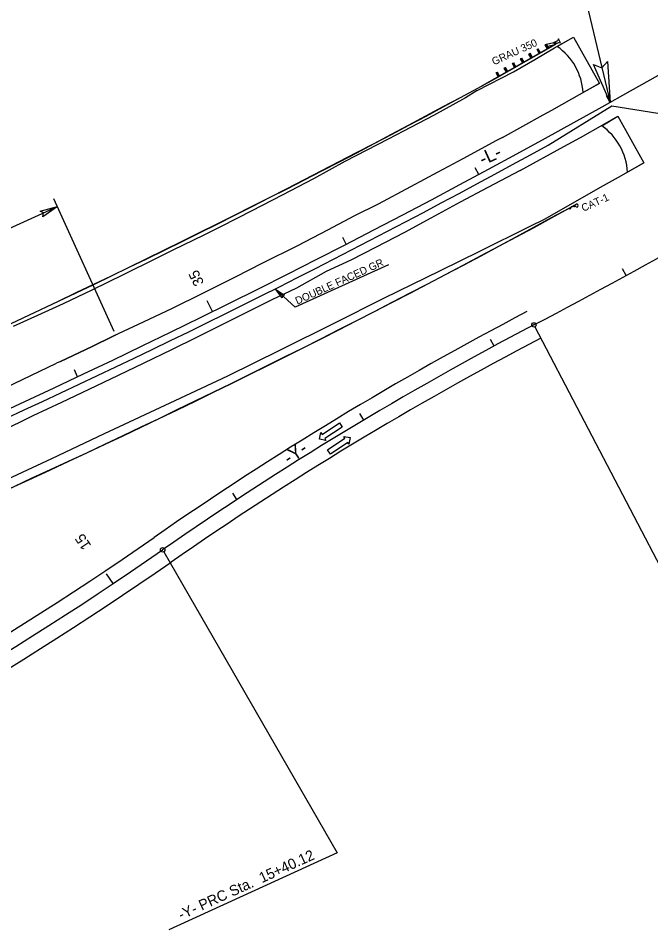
# Model space of a CAD drawing. Extents: x 2242984 to 2250974, y 661492 to 664681.
# Drawn here: x 2249828 to 2250250, y 663412 to 664020 of the extents above; entities that cross this region are included whole.
import ezdxf

# ---------------------------------------------------------------- set-up
doc = ezdxf.new("R2010")
doc.units = 0
for name, color, linetype in [('Prop Dimension', 7, 'Continuous'), ('Prop DSN Text', 7, 'Continuous'), ('Prop EOT Dash', 7, 'Continuous'), ('Prop Guardrail', 7, 'Continuous'), ('Prop Guardrail Anchor Unit CELL', 7, 'Continuous'), ('Prop Guardrail Double Faced', 7, 'Continuous'), ('Prop Horizontal Alignment', 7, 'Continuous'), ('Prop Horizontal Alignment Curve and Spiral Data', 7, 'Continuous'), ('Prop Horizontal Alignment Station Label', 7, 'Continuous'), ('Prop Horizontal Alignment Tick Label', 7, 'Continuous'), ('Prop Horizontal Alignment Tick Large', 7, 'Continuous'), ('Prop Horizontal Alignment Tick Small', 7, 'Continuous'), ('Prop Lane Arrow CELL', 7, 'Continuous'), ('Prop Paved Shoulder', 7, 'Continuous'), ('Prop Shade Medium', 7, 'Continuous'), ('Prop Terminator CELL', 7, 'Continuous'), ('Scratch_Level_2', 7, 'Continuous'), ('Scratch_Level_6', 7, 'Continuous'), ('Typical Terminator CELL', 7, 'Continuous')]:
    doc.layers.add(name, color=color, linetype=linetype)

# ---------------------------------------------------------------- blocks, each defined once
blk = doc.blocks.new('TERMINATOR')
at = {"layer": 'Typical Terminator CELL'}
blk.add_lwpolyline([(-0.469, 0.081), (0, 0), (-0.471, -0.083), (-0.411, 0)], close=True, dxfattribs=at)

msp = doc.modelspace()

# ---------------------------------------------------------------- linework, layer by layer
at = {"layer": 'Prop Dimension'}
for p, q in [((2250142.17, 664305.26), (2250223.29, 663964)), ((2250224.53, 663961.77), (2250255.11, 663956.78)), ((2249892.16, 663811.07), (2249851.91, 663899.68)), ((2249394.77, 663685.73), (2249854.28, 663894.46))]:
    msp.add_line(p, q, dxfattribs=at)
at = {"layer": 'Prop DSN Text'}
for p in [(2250075.36, 663855.62), (2250000.07, 663839)]:
    msp.add_line(p, (2250013.07, 663827.24), dxfattribs=at)
at = {"layer": 'Prop EOT Dash'}
for centre, radius, start, end in [((2251237.28, 661776.78), 2310, 117.57881, 124.80379), ((2251237.28, 661776.78), 2290, 117.57881, 124.80379), ((2248611.75, 665553.89), 2290, 294.41783, 304.80379), ((2248611.75, 665553.89), 2310, 294.41783, 304.80379)]:
    msp.add_arc(centre, radius, start, end, dxfattribs=at)
at = {"layer": 'Prop Guardrail'}
for radius, start, end in [(5678.58, 294.43013, 298.65426), (5778.08, 294.430126, 298.67506)]:
    msp.add_arc((2247423.42, 668962.88), radius, start, end, dxfattribs=at)
at = {"layer": 'Prop Guardrail Anchor Unit CELL'}
for p, q in [((2250146.43, 663979.76), (2250187.02, 664002.95)), ((2250179.95, 664002.43), (2250180.82, 664002.93)), ((2250181.47, 663999.77), (2250179.95, 664002.43)), ((2250181.57, 664001.6), (2250179.95, 664002.43)), ((2250180.82, 664002.93), (2250180.71, 664001.1)), ((2250180.82, 664002.93), (2250185.85, 664004)), ((2250182.33, 664000.27), (2250180.82, 664002.93)), ((2250181.57, 664001.6), (2250186.59, 664002.7)), ((2250185.85, 664004), (2250186.71, 664004.5)), ((2250185.85, 664004), (2250186.28, 664004.25)), ((2250186.59, 664002.7), (2250185.85, 664004)), ((2250187.46, 664003.2), (2250185.85, 664004)), ((2250188.22, 664005.08), (2250186.43, 664004.1)), ((2250186.43, 664004.1), (2250186.72, 664003.57)), ((2250186.71, 664004.5), (2250186.59, 664002.7)), ((2250187.46, 664003.2), (2250186.71, 664004.5)), ((2250186.72, 664003.57), (2250187.02, 664003.03)), ((2250187.02, 664003.03), (2250188.81, 664004.01)), ((2250188.84, 664006.4), (2250188.22, 664005.08)), ((2250188.81, 664004.01), (2250190.26, 664003.82)), ((2250190.26, 664003.82), (2250188.84, 664006.4)), ((2250168.97, 663996.25), (2250169.83, 663996.74)), ((2250170.52, 663993.52), (2250168.97, 663996.25)), ((2250170.61, 663995.38), (2250168.97, 663996.25)), ((2250169.83, 663996.74), (2250169.74, 663994.88)), ((2250171.39, 663994.02), (2250169.83, 663996.74)), ((2250174.51, 663999.25), (2250175.37, 663999.75)), ((2250175.99, 663996.65), (2250174.51, 663999.25)), ((2250176.12, 663998.45), (2250174.51, 663999.25)), ((2250175.37, 663999.75), (2250175.25, 663997.95)), ((2250175.25, 663997.95), (2250176.12, 663998.45)), ((2250175.25, 663997.95), (2250176.86, 663997.14)), ((2250176.86, 663997.14), (2250175.37, 663999.75)), ((2250175.99, 663996.65), (2250176.12, 663998.45)), ((2250180.71, 664001.1), (2250181.57, 664001.6)), ((2250180.71, 664001.1), (2250182.33, 664000.27)), ((2250181.47, 663999.77), (2250181.57, 664001.6)), ((2250158.07, 663989.92), (2250158.94, 663990.42)), ((2250159.58, 663987.27), (2250158.07, 663989.92)), ((2250159.69, 663989.09), (2250158.07, 663989.92)), ((2250158.94, 663990.42), (2250158.82, 663988.6)), ((2250160.45, 663987.77), (2250158.94, 663990.42)), ((2250163.54, 663993.03), (2250164.41, 663993.53)), ((2250165.05, 663990.4), (2250163.54, 663993.03)), ((2250165.17, 663992.21), (2250163.54, 663993.03)), ((2250164.41, 663993.53), (2250164.3, 663991.72)), ((2250164.3, 663991.72), (2250165.17, 663992.21)), ((2250164.3, 663991.72), (2250165.92, 663990.89)), ((2250165.92, 663990.89), (2250164.41, 663993.53)), ((2250165.05, 663990.4), (2250165.17, 663992.21)), ((2250165.05, 663990.4), (2250165.92, 663990.89)), ((2250169.74, 663994.88), (2250170.61, 663995.38)), ((2250169.74, 663994.88), (2250171.39, 663994.02)), ((2250170.52, 663993.52), (2250170.61, 663995.38)), ((2250147.15, 663983.63), (2250148.02, 663984.12)), ((2250148.02, 663984.12), (2250147.89, 663982.33)), ((2250149.5, 663981.52), (2250148.02, 663984.12)), ((2250152.59, 663986.8), (2250153.46, 663987.29)), ((2250154.11, 663984.15), (2250152.59, 663986.8)), ((2250154.22, 663985.97), (2250152.59, 663986.8)), ((2250153.46, 663987.29), (2250153.35, 663985.47)), ((2250153.35, 663985.47), (2250154.22, 663985.97)), ((2250153.35, 663985.47), (2250154.98, 663984.64)), ((2250154.98, 663984.64), (2250153.46, 663987.29)), ((2250154.11, 663984.15), (2250154.22, 663985.97)), ((2250158.82, 663988.6), (2250159.69, 663989.09)), ((2250158.82, 663988.6), (2250160.45, 663987.77)), ((2250159.58, 663987.27), (2250159.69, 663989.09)), ((2250148.64, 663981.02), (2250147.15, 663983.63)), ((2250148.76, 663982.82), (2250147.15, 663983.63)), ((2250147.89, 663982.33), (2250148.76, 663982.82)), ((2250147.89, 663982.33), (2250149.5, 663981.52)), ((2250148.76, 663982.82), (2250148.64, 663981.02)), ((2250148.64, 663981.02), (2250149.5, 663981.52)), ((2250149.5, 663981.52), (2250148.76, 663982.82)), ((2250195.98, 663893.45), (2250199.09, 663895.15)), ((2250195.98, 663893.45), (2250196.6, 663893.79)), ((2250196.37, 663892.74), (2250195.98, 663893.45)), ((2250195.98, 663893.45), (2250196.98, 663893.08)), ((2250196.6, 663893.79), (2250196.37, 663892.74)), ((2250196.98, 663893.08), (2250196.37, 663892.74)), ((2250196.6, 663893.79), (2250196.98, 663893.08)), ((2250199.21, 663894.75), (2250197.35, 663894.2)), ((2250198.71, 663894.94), (2250199.33, 663895.27)), ((2250199.1, 663894.23), (2250198.71, 663894.94)), ((2250198.71, 663894.94), (2250199.71, 663894.57)), ((2250199.09, 663895.15), (2250200.6, 663895.97)), ((2250199.21, 663895.21), (2250199.09, 663895.15)), ((2250199.33, 663895.27), (2250199.1, 663894.23)), ((2250199.71, 663894.57), (2250199.1, 663894.23)), ((2250199.33, 663895.27), (2250199.71, 663894.57)), ((2250200.66, 663894.2), (2250199.66, 663894.65))]:
    msp.add_line(p, q, dxfattribs=at)
msp.add_ellipse((2250201.08, 663895.1), major_axis=(-0.475, 0.872), ratio=0.995379, start_param=2.210226, end_param=6.283185, dxfattribs=at)
at = {"layer": 'Prop Guardrail Double Faced'}
msp.add_line((2250181.96, 663935.37), (2250224.53, 663961.77), dxfattribs=at)
msp.add_arc((2247423.42, 668962.88), 5734.58, 294.430126, 298.75316, dxfattribs=at)
at = {"layer": 'Prop Horizontal Alignment'}
for centre, radius, start, end in [((2247423.42, 668962.88), 5729.58, 294.43013, 308.28013), ((2248552.07, 666917.75), 3500, 297.57881, 302.00527), ((2251237.28, 661776.78), 2300, 117.57881, 124.80379), ((2248611.75, 665553.89), 2300, 294.41783, 304.80379)]:
    msp.add_arc(centre, radius, start, end, dxfattribs=at)
at = {"layer": 'Prop Horizontal Alignment Station Label'}
for p, q in [((2250173.15, 663814.11), (2250278.27, 663612.84)), ((2249925.26, 663664.03), (2250041.16, 663462.96)), ((2250041.16, 663462.96), (2249928.6, 663411.67))]:
    msp.add_line(p, q, dxfattribs=at)
for centre in [(2250172.45, 663815.44), (2250172.45, 663815.44), (2249924.52, 663665.33), (2249924.52, 663665.33)]:
    msp.add_circle(centre, 1.5, dxfattribs=at)
at = {"layer": 'Prop Horizontal Alignment Tick Large'}
for p, q in [((2249957.83, 663824.32), (2249954.29, 663831.49)), ((2249891.38, 663642.72), (2249886.93, 663649.37))]:
    msp.add_line(p, q, dxfattribs=at)
at = {"layer": 'Prop Horizontal Alignment Tick Small'}
for p, q in [((2250223.29, 663964), (2250220.84, 663968.36)), ((2250135.62, 663915.9), (2250133.25, 663920.3)), ((2250047.12, 663869.33), (2250044.83, 663873.78)), ((2250234.04, 663848.39), (2250231.64, 663852.78)), ((2250145.83, 663801.31), (2250143.45, 663805.71)), ((2249867.76, 663780.87), (2249865.63, 663785.39)), ((2250058.86, 663751.95), (2250056.3, 663756.25)), ((2249974.12, 663698.87), (2249971.38, 663703.05))]:
    msp.add_line(p, q, dxfattribs=at)
at = {"layer": 'Prop Lane Arrow CELL'}
for p, q in [((2250030.95, 663742.35), (2250042.65, 663750.03)), ((2250044.46, 663747.27), (2250032.76, 663739.59)), ((2250042.65, 663750.03), (2250044.46, 663747.27)), ((2250029.25, 663739.2), (2250030.12, 663743.6)), ((2250030.12, 663743.6), (2250030.95, 663742.35)), ((2250046.29, 663739.77), (2250045.45, 663741.02)), ((2250045.45, 663741.02), (2250049.8, 663740.2)), ((2250033.58, 663738.33), (2250029.25, 663739.2)), ((2250032.76, 663739.59), (2250033.58, 663738.33)), ((2250034.66, 663731.97), (2250046.29, 663739.77)), ((2250048.13, 663737.03), (2250036.5, 663729.23)), ((2250048.96, 663735.79), (2250048.13, 663737.03)), ((2250049.8, 663740.2), (2250048.96, 663735.79)), ((2250036.5, 663729.23), (2250034.66, 663731.97))]:
    msp.add_line(p, q, dxfattribs=at)
at = {"layer": 'Prop Paved Shoulder'}
for p, q in [((2249877.49, 663801.04), (2249891.38, 663807.97)), ((2249891.38, 663807.97), (2249893.19, 663808.8)), ((2249856.27, 663791.12), (2249877.49, 663801.04)), ((2249437.63, 663591.42), (2249853.74, 663789.97))]:
    msp.add_line(p, q, dxfattribs=at)
for points in [[(2250158.72, 663984.49), (2250173.08, 663992.65), (2250186.18, 664000.31), (2250198.89, 664007.57)], [(2250134.59, 663971.94), (2250158.72, 663984.49)], [(2250134.59, 663971.94), (2250126.82, 663967.1), (2250105.33, 663955.19), (2250085.39, 663944.79), (2250075.11, 663939.48), (2250046.26, 663924.42), (2250025.26, 663912.92), (2250004.43, 663901.99), (2249983.97, 663891.5), (2249963.67, 663881.2), (2249951.96, 663875.41), (2249931.42, 663865.38), (2249920.19, 663859.82), (2249898.1, 663848.94), (2249877.27, 663838.63), (2249858.19, 663829.56), (2249843.45, 663822.95), (2249824.73, 663814.35)], [(2250178.7, 663955.71), (2250184.3, 663958.78), (2250216.15, 663976.74)], [(2250151.36, 663940.62), (2250178.7, 663955.71)], [(2250192.4, 663934.62), (2250203.58, 663940.63), (2250218.57, 663948.92), (2250228.5, 663954.7)], [(2250151.36, 663940.62), (2250147.39, 663938.44), (2250124.88, 663926.39), (2250108.36, 663917.42), (2250090.02, 663907.52), (2250068.46, 663896.14), (2250052.71, 663888.16), (2250034.57, 663878.68), (2250014.61, 663868.32), (2249991.28, 663856.62), (2249972.95, 663847.39), (2249951.67, 663836.73), (2249930.54, 663826.11), (2249908.26, 663815.71), (2249891.38, 663807.97), (2249877.49, 663801.04), (2249856.27, 663791.12), (2249853.74, 663789.97)], [(2250163.18, 663918.53), (2250192.4, 663934.62)], [(2250216.95, 663907.43), (2250229.03, 663914.01), (2250245.85, 663923.72)], [(2250163.18, 663918.53), (2250141.76, 663907.17), (2250123.19, 663897.33), (2250103.59, 663886.75), (2250085.93, 663877.2), (2250066.71, 663867.19), (2250050.24, 663858.7), (2250033.81, 663851.08), (2250013.9, 663840.08), (2249997.54, 663832.27), (2249982.72, 663824.86), (2249962.36, 663814.71), (2249947.05, 663807.05), (2249930.38, 663798.85), (2249911.87, 663789.95), (2249894.79, 663781.72), (2249875.22, 663772.32), (2249857.01, 663763.64), (2249837.93, 663754.68), (2249815.49, 663743.88), (2249803.29, 663738.06), (2249784.26, 663729.26), (2249767.73, 663721.96), (2249763, 663719.65)], [(2250179.91, 663886.23), (2250216.95, 663907.43)], [(2249763.05, 663685.31), (2249811.06, 663707.92), (2249850.56, 663726.37), (2249885.63, 663742.92), (2249932.97, 663765.08), (2249967.97, 663781.54), (2250003.28, 663798.87), (2250039.45, 663816.82), (2250072.29, 663833.2), (2250110.04, 663851.84), (2250136.3, 663864.69), (2250169.45, 663881.11), (2250179.91, 663886.23)]]:
    msp.add_lwpolyline(points, dxfattribs=at)
at = {"layer": 'Prop Shade Medium'}
for p, q in [((2250188.01, 664001.35), (2250198.89, 664007.57)), ((2250198.89, 664007.57), (2250216.24, 663976.59)), ((2250216.24, 663976.59), (2250205.25, 663970.59)), ((2250217.69, 663948.44), (2250228.5, 663954.7)), ((2250228.5, 663954.7), (2250245.85, 663923.72)), ((2250245.85, 663923.72), (2250234.94, 663917.42))]:
    msp.add_line(p, q, dxfattribs=at)
for centre, radius, start, end in [((2250164.87, 663968.16), 40.46, 3.44001, 55.1119), ((2250194.29, 663915.12), 40.72, 3.24076, 54.91264)]:
    msp.add_arc(centre, radius, start, end, dxfattribs=at)
at = {"layer": 'Prop Terminator CELL'}
for points in [[(2250221.57, 663991.34), (2250223.29, 663964), (2250212.34, 663989.3), (2250217.81, 663987.06)], [(2250004.3, 663833.61), (2250000.07, 663839), (2250005.91, 663835.34), (2250004.47, 663835.02)]]:
    msp.add_lwpolyline(points, close=True, dxfattribs=at)
at = {"layer": 'Scratch_Level_2'}
for points in [[(2250158.72, 663984.49), (2250173.08, 663992.65), (2250186.18, 664000.31), (2250198.89, 664007.57)], [(2250134.59, 663971.94), (2250158.72, 663984.49)], [(2250216.95, 663907.43), (2250229.03, 663914.01), (2250245.85, 663923.72)], [(2250179.91, 663886.23), (2250216.95, 663907.43)]]:
    msp.add_lwpolyline(points, dxfattribs=at)
at = {"layer": 'Scratch_Level_6'}
for p, q in [((2250146.38, 663979.85), (2250186.97, 664003.03)), ((2250196.03, 663893.37), (2250200.65, 663895.88))]:
    msp.add_line(p, q, dxfattribs=at)
for radius, start, end in [(5678.48, 294.43013, 298.65426), (5778.18, 294.430126, 298.67506)]:
    msp.add_arc((2247423.42, 668962.88), radius, start, end, dxfattribs=at)

# ---------------------------------------------------------------- block references
at = {"layer": 'Prop Dimension', "xscale": 24.999999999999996, "yscale": 24.999999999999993, "rotation": 24.430125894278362}
msp.add_blockref('TERMINATOR', (2249854.28, 663894.46), dxfattribs=at)

# ---------------------------------------------------------------- texts
at = {"layer": 'Prop DSN Text'}
msp.add_text('DOUBLE FACED GR', height=5, rotation=24.49794, dxfattribs=at).set_placement((2250014.43, 663828.89))
at = {"layer": 'Prop Guardrail Anchor Unit CELL'}
for s, p in [('GRAU 350', (2250145.74, 663988.67)), ('CAT-1', (2250205.51, 663890.88))]:
    msp.add_text(s, height=5, rotation=24.49794, dxfattribs=at).set_placement(p)
at = {"layer": 'Prop Horizontal Alignment Curve and Spiral Data'}
for s, rotation, p in [('-L-', 24.43013, (2250138.32, 663921.69)), ('-Y-', 34.14714, (2250008.86, 663721.93))]:
    msp.add_text(s, height=9, rotation=rotation, dxfattribs=at).set_placement(p)
at = {"layer": 'Prop Horizontal Alignment Station Label'}
msp.add_text('-Y- PRC Sta.  15+40.12', height=7, rotation=24.49794, dxfattribs=at).set_placement((2249936.87, 663418.15))
at = {"layer": 'Prop Horizontal Alignment Tick Label'}
for s, rotation, p in [('35', 116.25316, (2249952.37, 663843.48)), ('15', 123.80441, (2249877.11, 663668.18))]:
    msp.add_text(s, height=7, rotation=rotation, dxfattribs=at).set_placement(p)

doc.saveas('drawing.dxf')
